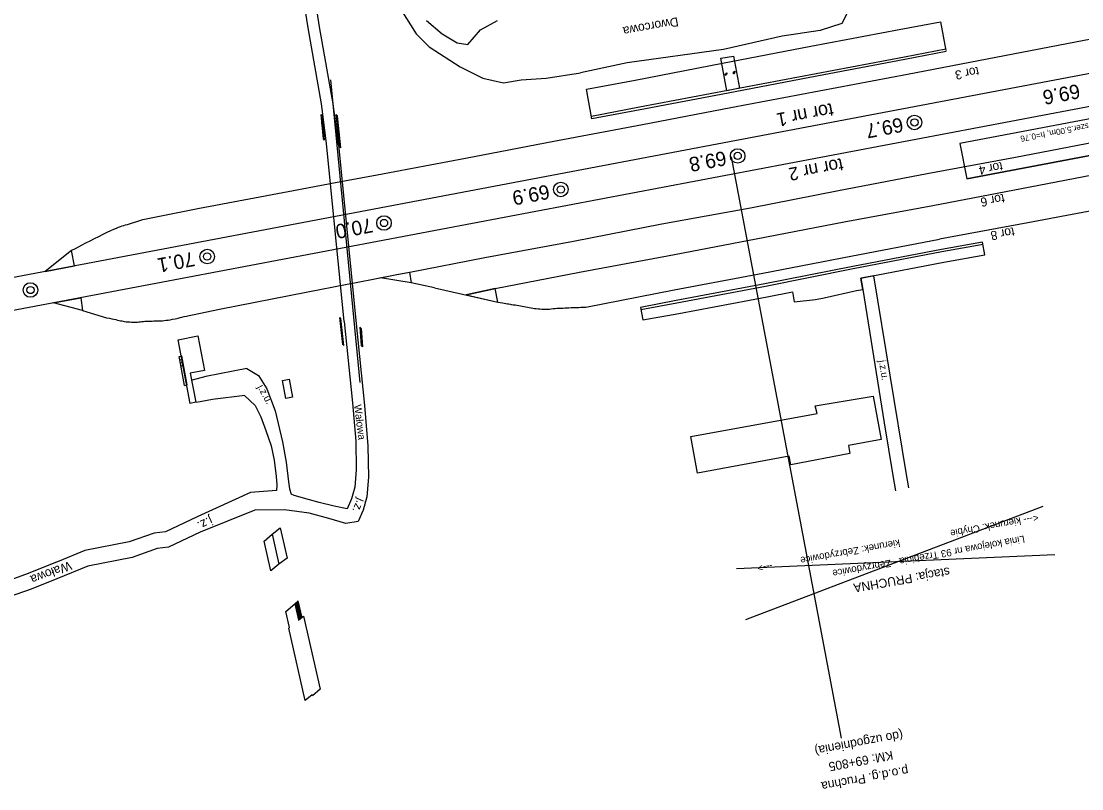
# Model space of a CAD drawing. Extents: x 6541740 to 6556805, y 5525233 to 5530361.
# Drawn here: x 6555063.1 to 6555210.5, y 5525689.7 to 5525796.3 of the extents above; entities that cross this region are included whole.
import ezdxf

# ---------------------------------------------------------------- set-up
doc = ezdxf.new("R2010")
doc.units = 0
for name, color, linetype in [('Default', 7, 'Continuous'), ('TOR_PS_OPIS_T-numeracja torow i rozjazdow', 7, 'Continuous'), ('TOR_SCH-budynki', 7, 'Continuous'), ('TOR_SCH-hektometry', 7, 'Continuous'), ('TOR_SCH-obiekty istniejace', 7, 'Continuous'), ('TOR_SCH-obiekty projektowane', 7, 'Continuous'), ('TOR_SCH-opisy glowne', 7, 'Continuous'), ('TOR_SCH-opisy istniejace', 7, 'Continuous'), ('TOR_SCH-perony', 7, 'Continuous'), ('TOR_SCH-pochylniki projektowane', 7, 'Continuous'), ('TOR_SCH-przejazdy+drogi istniejace', 7, 'Continuous'), ('TOR_SCH-tory i rozjazdy do rozbiorki', 7, 'Continuous'), ('TOR_SCH-tory projektowane', 7, 'Continuous')]:
    doc.layers.add(name, color=color, linetype=linetype)

# ---------------------------------------------------------------- blocks, each defined once
blk = doc.blocks.new('4010_1')
at = {"layer": 'Default'}
for radius in [0.75, 0.375]:
    blk.add_circle((0, 0), radius, dxfattribs=at)
blk = doc.blocks.new('311_3')
at = {"layer": 'Default'}
blk.add_circle((0, 0), 0.25, dxfattribs=at)
blk = doc.blocks.new('POINT_DISPLAY')
at = {"layer": 'Default'}
blk.add_line((0, 0), (0, 0), dxfattribs=at)

msp = doc.modelspace()

# ---------------------------------------------------------------- linework, layer by layer
at = {"layer": 'Default'}
for p, q in [((6555173.44, 5525742.92), (6555181.49, 5525744.28)), ((6555181.49, 5525744.28), (6555182.58, 5525738.22)), ((6555173.69, 5525741.85), (6555173.44, 5525742.92)), ((6555156.16, 5525738.66), (6555173.69, 5525741.85)), ((6555157.08, 5525733.58), (6555156.16, 5525738.66)), ((6555182.58, 5525738.22), (6555178.07, 5525737.42)), ((6555178.07, 5525737.42), (6555178.25, 5525736.3)), ((6555169.8, 5525735.92), (6555157.08, 5525733.58)), ((6555170.03, 5525734.72), (6555169.8, 5525735.92)), ((6555178.25, 5525736.3), (6555170.03, 5525734.72))]:
    msp.add_line(p, q, dxfattribs=at)
at = {"layer": 'TOR_SCH-budynki'}
for p, q in [((6555084.92, 5525752.1), (6555087.65, 5525752.65)), ((6555086.6, 5525743.26), (6555084.92, 5525752.1)), ((6555087.65, 5525752.65), (6555088.57, 5525747.83)), ((6555085.06, 5525749.79), (6555085.42, 5525749.88)), ((6555085.15, 5525749.29), (6555085.52, 5525749.37)), ((6555085.23, 5525748.88), (6555085.6, 5525748.96)), ((6555085.31, 5525748.46), (6555085.68, 5525748.54)), ((6555088.57, 5525747.83), (6555086.61, 5525747.44)), ((6555086.61, 5525747.44), (6555087.37, 5525743.42)), ((6555085.83, 5525745.76), (6555086.19, 5525745.84)), ((6555099.43, 5525746.45), (6555100.33, 5525746.6)), ((6555099.91, 5525743.92), (6555099.43, 5525746.45)), ((6555100.33, 5525746.6), (6555100.8, 5525744.1)), ((6555100.8, 5525744.1), (6555099.91, 5525743.92)), ((6555087.37, 5525743.42), (6555086.6, 5525743.26)), ((6555096.86, 5525724.12), (6555097.98, 5525725.07)), ((6555097.98, 5525725.07), (6555099.11, 5525725.97)), ((6555097.98, 5525725.07), (6555098.93, 5525720.91)), ((6555099.11, 5525725.97), (6555100.06, 5525721.78)), ((6555097.81, 5525720), (6555096.86, 5525724.12)), ((6555100.06, 5525721.78), (6555098.93, 5525720.91)), ((6555098.93, 5525720.91), (6555097.81, 5525720)), ((6555099.91, 5525714.34), (6555101.13, 5525715.42)), ((6555101.59, 5525715.85), (6555101.13, 5525715.42)), ((6555101.13, 5525715.42), (6555101.66, 5525713.13)), ((6555101.24, 5525715.52), (6555101.77, 5525713.22)), ((6555101.34, 5525715.62), (6555101.88, 5525713.31)), ((6555101.45, 5525715.72), (6555101.99, 5525713.4)), ((6555101.56, 5525715.82), (6555102.1, 5525713.48)), ((6555102.13, 5525713.51), (6555101.59, 5525715.85)), ((6555100.42, 5525712.11), (6555099.91, 5525714.34)), ((6555101.66, 5525713.13), (6555102.35, 5525713.69)), ((6555101.66, 5525713.13), (6555102.13, 5525713.51)), ((6555102.35, 5525713.69), (6555104.65, 5525703.58)), ((6555100.32, 5525712.02), (6555100.42, 5525712.11)), ((6555102.59, 5525701.99), (6555100.32, 5525712.02)), ((6555103.55, 5525702.8), (6555102.59, 5525701.99)), ((6555103.58, 5525702.65), (6555103.55, 5525702.8)), ((6555104.65, 5525703.58), (6555103.58, 5525702.65))]:
    msp.add_line(p, q, dxfattribs=at)
for points in [[(6555085.83, 5525745.76), (6555085.15, 5525749.29), (6555085.06, 5525749.79)], [(6555086.19, 5525745.84), (6555085.52, 5525749.37), (6555085.42, 5525749.88)]]:
    msp.add_lwpolyline(points, dxfattribs=at)
at = {"layer": 'TOR_SCH-obiekty istniejace'}
for points in [[(6555142.42, 5525782.77), (6555141.64, 5525786.91), (6555148.4, 5525788.13), (6555160.54, 5525790.49), (6555172.83, 5525792.87), (6555185.11, 5525795.18), (6555190.83, 5525796.24)], [(6555190.83, 5525796.24), (6555191.59, 5525792.28)], [(6555191.56, 5525792.45), (6555185.83, 5525791.36), (6555173.57, 5525789.03), (6555161.28, 5525786.7), (6555149.04, 5525784.38), (6555142.36, 5525783.11)], [(6555191.62, 5525792.11), (6555185.9, 5525791.02), (6555173.64, 5525788.69), (6555161.34, 5525786.36), (6555149.1, 5525784.03), (6555142.42, 5525782.77)], [(6555162.07, 5525791.47), (6555162.91, 5525787.02), (6555161.15, 5525786.68), (6555160.31, 5525791.21), (6555162.07, 5525791.47)], [(6555149.15, 5525756.57), (6555149.5, 5525754.84), (6555154.47, 5525755.72), (6555166.76, 5525758.06), (6555170.26, 5525758.75), (6555170.51, 5525757.34), (6555173.49, 5525757.67), (6555174.67, 5525757.93), (6555179.17, 5525758.93), (6555180.04, 5525759.07), (6555179.76, 5525760.63), (6555180.71, 5525760.81), (6555191.3, 5525762.87), (6555197, 5525763.89), (6555196.68, 5525765.65)], [(6555196.68, 5525765.65), (6555190.97, 5525764.64), (6555178.66, 5525762.26)], [(6555196.75, 5525765.31), (6555191.03, 5525764.29), (6555178.72, 5525761.92)], [(6555178.66, 5525762.26), (6555166.44, 5525759.85), (6555154.12, 5525757.54), (6555149.15, 5525756.57)], [(6555178.72, 5525761.92), (6555166.51, 5525759.51), (6555154.19, 5525757.19), (6555149.22, 5525756.23)]]:
    msp.add_lwpolyline(points, dxfattribs=at)
at = {"layer": 'TOR_SCH-obiekty projektowane'}
msp.add_line((6555106.1, 5525788.21), (6555110.17, 5525746.15), dxfattribs=at)
at = {"layer": 'TOR_SCH-opisy glowne'}
msp.add_lwpolyline([(6555177.07, 5525696.76), (6555161.81, 5525777.51), (6555161.81, 5525777.51), (6555161.81, 5525777.51)], dxfattribs=at)
at = {"layer": 'TOR_SCH-perony'}
for p, q in [((6555242.67, 5525788.69), (6555193.54, 5525779.37)), ((6555193.54, 5525779.37), (6555194.48, 5525774.46)), ((6555216.35, 5525778.61), (6555194.48, 5525774.46)), ((6555216.34, 5525778.53), (6555194.49, 5525774.38))]:
    msp.add_line(p, q, dxfattribs=at)
at = {"layer": 'TOR_SCH-pochylniki projektowane'}
for p, q in [((6555163.81, 5525713.25), (6555205.11, 5525728.97)), ((6555206.73, 5525722.21), (6555162.48, 5525720.28))]:
    msp.add_line(p, q, dxfattribs=at)
at = {"layer": 'TOR_SCH-przejazdy+drogi istniejace'}
for p, q in [((6555104.97, 5525783.17), (6555104.79, 5525783.36)), ((6555105.1, 5525780), (6555104.79, 5525783.36)), ((6555105.07, 5525782.13), (6555104.85, 5525782.77)), ((6555105.28, 5525779.81), (6555104.97, 5525783.17)), ((6555107.07, 5525783.2), (6555106.89, 5525783.36)), ((6555107.37, 5525778.89), (6555106.89, 5525783.36)), ((6555107.54, 5525778.74), (6555107.07, 5525783.2)), ((6555105.12, 5525781.5), (6555104.91, 5525782.14)), ((6555107.27, 5525781.31), (6555107.04, 5525781.96)), ((6555107.34, 5525780.61), (6555107.12, 5525781.26)), ((6555105.28, 5525779.81), (6555105.1, 5525780)), ((6555107.98, 5525754.63), (6555105.55, 5525779.33)), ((6555107.2, 5525779.15), (6555109.65, 5525754.29)), ((6555107.54, 5525778.74), (6555107.37, 5525778.89)), ((6555107.54, 5525755.04), (6555107.39, 5525755.17)), ((6555107.79, 5525751.44), (6555107.39, 5525755.17)), ((6555107.94, 5525751.31), (6555107.54, 5525755.04)), ((6555107.72, 5525753.38), (6555107.53, 5525753.9)), ((6555107.78, 5525752.82), (6555107.59, 5525753.34)), ((6555110.19, 5525753.83), (6555110.34, 5525753.64)), ((6555110.19, 5525753.83), (6555110.37, 5525751.31)), ((6555110.34, 5525753.64), (6555110.52, 5525751.12)), ((6555107.94, 5525751.31), (6555107.79, 5525751.44)), ((6555110.28, 5525752.59), (6555110.45, 5525752.08)), ((6555110.31, 5525752.13), (6555110.49, 5525751.62)), ((6555110.37, 5525751.31), (6555110.52, 5525751.12)), ((6555101.06, 5525730.47), (6555100.61, 5525730.67))]:
    msp.add_line(p, q, dxfattribs=at)
for points in [[(6555103.82, 5525815.1), (6555105.24, 5525816.49), (6555106.98, 5525815.22), (6555108.97, 5525811.49), (6555111.71, 5525806.01), (6555113.9, 5525801.86), (6555115.87, 5525797.97), (6555117.99, 5525794.58), (6555119.79, 5525792.78)], [(6555107.2, 5525779.15), (6555106.47, 5525784.86), (6555104.58, 5525795.56), (6555102.84, 5525806.59), (6555102.75, 5525813.58)], [(6555105.55, 5525779.33), (6555104.85, 5525784.85), (6555102.97, 5525795.43), (6555101.97, 5525801.78), (6555101.17, 5525806.84), (6555101.17, 5525806.84)], [(6555179.19, 5525798.81), (6555178.27, 5525798.27), (6555177.11, 5525796.01), (6555174.11, 5525795.03), (6555168.85, 5525794.24), (6555160.68, 5525792.4), (6555147.29, 5525790.56), (6555140.81, 5525789.16)], [(6555119.44, 5525796.45), (6555121.59, 5525794.59), (6555123.69, 5525793.33), (6555125.15, 5525793.11), (6555126.95, 5525795.15), (6555129.31, 5525796.42)], [(6555119.79, 5525792.78), (6555124.1, 5525790.01), (6555127.24, 5525788.41), (6555130.13, 5525787.79), (6555132.6, 5525788.19), (6555136.04, 5525788.43), (6555140.81, 5525789.16)], [(6555181.59, 5525760.98), (6555179.76, 5525760.63), (6555180.04, 5525759.07)], [(6555186.43, 5525731.51), (6555186.13, 5525733.36), (6555181.59, 5525760.98)], [(6555180.04, 5525759.07), (6555183.02, 5525740.54), (6555184.21, 5525733.23), (6555184.59, 5525731.13)], [(6555109.65, 5525754.29), (6555110.83, 5525742.95), (6555111.29, 5525737.35), (6555111.37, 5525733.03), (6555111.16, 5525730.28), (6555110.65, 5525728.44), (6555109.94, 5525726.85), (6555108.24, 5525726.56), (6555105.86, 5525727.26), (6555103.11, 5525728), (6555099.7, 5525728.48)], [(6555107.98, 5525754.63), (6555109.15, 5525743.35), (6555109.6, 5525738.01), (6555109.67, 5525734.05), (6555109.48, 5525731.64), (6555109.03, 5525730), (6555108.4, 5525728.6), (6555106.6, 5525728.97), (6555104.54, 5525729.51), (6555103.16, 5525729.88), (6555101.06, 5525730.47)], [(6555094.45, 5525748.09), (6555088.76, 5525746.97), (6555086.89, 5525746.48)], [(6555094.45, 5525748.09), (6555096.08, 5525747.13), (6555097.27, 5525745.29), (6555098.41, 5525742.2), (6555099.42, 5525737.92), (6555099.95, 5525735.07), (6555100.27, 5525732.38), (6555100.39, 5525731.37), (6555100.61, 5525730.67)], [(6555094.18, 5525744.35), (6555089.69, 5525743.81), (6555087.47, 5525743.4)], [(6555094.17, 5525744.35), (6555095.64, 5525742.97), (6555096.4, 5525741.38), (6555097.12, 5525739.51), (6555097.86, 5525737.35), (6555098.28, 5525735.38), (6555098.54, 5525733.08), (6555098.63, 5525731.95), (6555098.57, 5525731.15)], [(6555098.57, 5525731.15), (6555095, 5525730.9), (6555087.57, 5525727.52), (6555083.16, 5525725.42), (6555081.62, 5525725.24), (6555078.11, 5525724.01), (6555071.95, 5525722.81), (6555068.4, 5525721.36), (6555067.65, 5525721.06), (6555064.08, 5525719.61), (6555060.11, 5525718.2), (6555058.6, 5525718.09)], [(6555099.7, 5525728.48), (6555095.6, 5525728.43), (6555088.01, 5525725.37), (6555083.59, 5525723.27), (6555082.03, 5525723.09), (6555078.53, 5525721.86), (6555072.37, 5525720.65), (6555068.08, 5525718.91), (6555064.51, 5525717.46), (6555060.52, 5525716.05), (6555059.4, 5525715.97), (6555059.4, 5525715.97), (6555059.4, 5525715.97)]]:
    msp.add_lwpolyline(points, dxfattribs=at)
at = {"layer": 'TOR_SCH-tory i rozjazdy do rozbiorki'}
for p, q in [((6555188.97, 5525775.16), (6555201.23, 5525777.46)), ((6555106.77, 5525773.91), (6555108.06, 5525774.15)), ((6555128.98, 5525759.21), (6555140.67, 5525761.48)), ((6555108.2, 5525759.77), (6555109.67, 5525760.06)), ((6555120.54, 5525759.31), (6555117.31, 5525760.02)), ((6555120.54, 5525759.31), (6555129.33, 5525757.31))]:
    msp.add_line(p, q, dxfattribs=at)
for points in [[(6555186.25, 5525789), (6555198.53, 5525791.32), (6555210.81, 5525793.69), (6555223.1, 5525796)], [(6555137.14, 5525779.66), (6555149.43, 5525782), (6555161.69, 5525784.33), (6555173.99, 5525786.67), (6555186.25, 5525789)], [(6555201.23, 5525777.46), (6555213.53, 5525779.81), (6555225.78, 5525782.1)], [(6555108.06, 5525774.15), (6555112.6, 5525775), (6555124.86, 5525777.31), (6555137.14, 5525779.66)], [(6555189.79, 5525770.76), (6555202.07, 5525773.1), (6555214.35, 5525775.45), (6555226.59, 5525777.73)], [(6555139.85, 5525765.8), (6555152.12, 5525768.17), (6555164.42, 5525770.42), (6555176.66, 5525772.84), (6555188.97, 5525775.16)], [(6555087.91, 5525770.37), (6555100.2, 5525772.68), (6555106.77, 5525773.91)], [(6555140.67, 5525761.48), (6555152.93, 5525763.76), (6555165.23, 5525766.1), (6555177.47, 5525768.45), (6555189.79, 5525770.76)], [(6555215.27, 5525770.65), (6555202.98, 5525768.35), (6555190.7, 5525766.04)], [(6555077.88, 5525768.11), (6555080.01, 5525768.78), (6555087.91, 5525770.37)], [(6555141.58, 5525756.63), (6555153.84, 5525759.01), (6555166.15, 5525761.33), (6555178.37, 5525763.68), (6555190.7, 5525766.04)], [(6555070.11, 5525764.51), (6555070.11, 5525764.51)], [(6555117.12, 5525761.49), (6555127.55, 5525763.5), (6555139.85, 5525765.8)], [(6555109.67, 5525760.06), (6555115.3, 5525761.14), (6555117.12, 5525761.49)], [(6555090.67, 5525756.33), (6555102.94, 5525758.73), (6555108.2, 5525759.77)], [(6555124.94, 5525758.31), (6555128.36, 5525759.07), (6555128.98, 5525759.21)], [(6555071.66, 5525756.16), (6555075, 5525755.16)], [(6555086.92, 5525755.56), (6555090.67, 5525756.33)]]:
    msp.add_lwpolyline(points, dxfattribs=at)
for points in [[(6555066.48, 5525761.57), (6555070.54, 5525762.34), (6555070.11, 5525764.51)], [(6555113.02, 5525760.7), (6555115.3, 5525761.14), (6555117.09, 5525761.48), (6555117.31, 5525760.02)], [(6555124.94, 5525758.31), (6555129.33, 5525757.31), (6555128.98, 5525759.21)], [(6555067.62, 5525757.2), (6555071.39, 5525757.91), (6555071.66, 5525756.16)]]:
    msp.add_lwpolyline(points, close=True, dxfattribs=at)
for points in [[(6555070.11, 5525764.51), (6555070.11, 5525764.51), (6555070.11, 5525764.51), (6555070.11, 5525764.51), (6555076.45, 5525767.77), (6555077.18, 5525767.89), (6555077.88, 5525768.11)], [(6555129.33, 5525757.31), (6555130.3, 5525757.15), (6555131.27, 5525757), (6555132.24, 5525756.84), (6555133.21, 5525756.69), (6555134.2, 5525756.44), (6555135.15, 5525756.38), (6555136.24, 5525756.31), (6555137.29, 5525756.46), (6555138.36, 5525756.5), (6555139.43, 5525756.55), (6555140.51, 5525756.59), (6555141.58, 5525756.63)], [(6555075, 5525755.16), (6555076.08, 5525754.96), (6555077.19, 5525754.63), (6555078.25, 5525754.56), (6555079.09, 5525754.5), (6555079.89, 5525754.64), (6555080.71, 5525754.67), (6555081.53, 5525754.71), (6555082.36, 5525754.69), (6555083.17, 5525754.79), (6555084.44, 5525754.95), (6555085.67, 5525755.3), (6555086.92, 5525755.56)]]:
    msp.add_open_spline(points, degree=3, dxfattribs=at)
at = {"layer": 'TOR_SCH-tory projektowane'}
for p, q in [((6555221.45, 5525790.95), (6555010.48, 5525750.96)), ((6555222.13, 5525786.49), (6554997.05, 5525743.82))]:
    msp.add_line(p, q, dxfattribs=at)

# ---------------------------------------------------------------- block references
at = {"layer": 'TOR_SCH-budynki', "xscale": 0.30824718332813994, "yscale": 0.8110374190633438, "rotation": -26.43658286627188}
msp.add_blockref('POINT_DISPLAY', (6555101.13, 5525715.42), dxfattribs=at)
at = {"layer": 'TOR_SCH-hektometry', "xscale": 1.345963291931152, "yscale": 1.345963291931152}
for p in [(6555187.22, 5525782.28), (6555162.66, 5525777.62), (6555138.09, 5525772.97), (6555113.53, 5525768.31), (6555088.97, 5525763.65), (6555064.41, 5525759)]:
    msp.add_blockref('4010_1', p, dxfattribs=at)
at = {"layer": 'TOR_SCH-obiekty istniejace', "xscale": 0.30824718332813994, "yscale": 0.8110374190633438, "rotation": -26.43658286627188}
for p in [(6555161.05, 5525788.97), (6555162.17, 5525789.2)]:
    msp.add_blockref('311_3', p, dxfattribs=at)

# ---------------------------------------------------------------- texts
at = {"layer": 'TOR_PS_OPIS_T-numeracja torow i rozjazdow'}
for s, height, p in [('tor nr 1', 1.875, (6555175.75, 5525784.98)), ('tor nr 2', 1.8, (6555177.12, 5525777.33))]:
    msp.add_text(s, height=height, rotation=190.7101, dxfattribs=at).set_placement(p)
at = {"layer": 'TOR_SCH-hektometry'}
for s, p in [('69.6', (6555210.01, 5525787.64)), ('69.7', (6555185.44, 5525782.98)), ('69.8', (6555160.88, 5525778.33)), ('69.9', (6555136.32, 5525773.67)), ('70.0', (6555111.76, 5525769.02)), ('70.1', (6555087.03, 5525764.33))]:
    msp.add_text(s, height=2, rotation=190.7691, dxfattribs=at).set_placement(p)
at = {"layer": 'TOR_SCH-opisy glowne'}
for s, height, rotation, p in [('<--- kierunek: Chybie', 1, 190.3205, (6555204.36, 5525727.88)), ('Linia kolejowa nr 93 Trzebinia - Zebrzydowice', 1, 190.2451, (6555202.45, 5525724.91)), ('kierunek: Zebrzydowice', 1, 190.2465, (6555185.11, 5525724.38)), (' --->', 1, 190.2465, (6555167.78, 5525721.24)), ('stacja: PRUCHNA', 1.25, 189.7564, (6555192.03, 5525720.5)), ('(do uzgodnienia)', 1.25, 190.5522, (6555185.51, 5525697.83)), ('KM: 69+805', 1.25, 190.5522, (6555184.12, 5525695.03)), ('p.o.d.g. Pruchna', 1.25, 190.5522, (6555186.25, 5525692.88))]:
    msp.add_text(s, height=height, rotation=rotation, dxfattribs=at).set_placement(p)
at = {"layer": 'TOR_SCH-opisy istniejace'}
for s, rotation, p in [('tor 3', 190.6989, (6555196.06, 5525790.04)), ('tor 4', 190.6794, (6555199.35, 5525776.81)), ('tor 6', 190.7255, (6555199.59, 5525772.38)), ('tor 8', 190.6823, (6555200.99, 5525767.73))]:
    msp.add_text(s, height=1.25, rotation=rotation, dxfattribs=at).set_placement(p)
at = {"layer": 'TOR_SCH-perony'}
msp.add_text('dł. 200m, szer.5.00m, h=0.76', height=0.84, rotation=190.7075, dxfattribs=at).set_placement((6555216.2, 5525783.1))
at = {"layer": 'TOR_SCH-przejazdy+drogi istniejace'}
for s, height, rotation, p in [('Dworcowa', 1.25, 190.2125, (6555154.31, 5525796.9)), ('j.z.u.', 1, 279.3277, (6555182.25, 5525749.19)), ('j.z.u.', 1.007, 298.6638, (6555095.92, 5525745.53)), ('Wałowa', 1.035, 277.3343, (6555109.36, 5525743.03)), ('j.z.', 1.181, 245.917, (6555109.91, 5525730.21)), ('j.z.', 1.248, 205.0108, (6555089.38, 5525727.6)), ('Wałowa', 1.249, 200.5957, (6555069.84, 5525721.37))]:
    msp.add_text(s, height=height, rotation=rotation, dxfattribs=at).set_placement(p)

doc.saveas('drawing.dxf')
